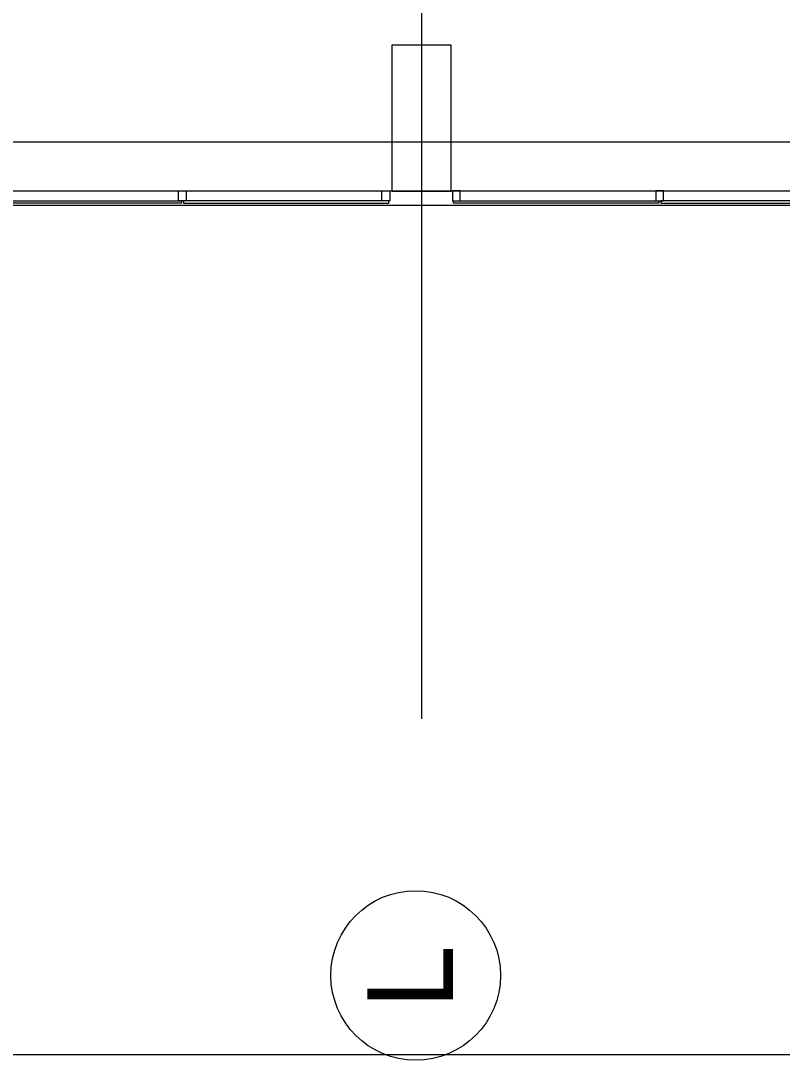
# Model space of a CAD drawing. Extents: x -264205 to -263659, y -1242401 to -1242060.
# Drawn here: x -263845.56 to -263837.78, y -1242250.2 to -1242239.57 of the extents above; entities that cross this region are included whole.
import ezdxf

# ---------------------------------------------------------------- set-up
doc = ezdxf.new("R2010")
doc.units = 0
for name, color, linetype in [('OBRUBNIKY_KOMUNIKACIE_PROJEKT', 7, 'Continuous'), ('OSI_STAVBY_KFA', 7, 'Continuous'), ('SITUACIA_DSP_2D', 7, 'Continuous')]:
    doc.layers.add(name, color=color, linetype=linetype)

msp = doc.modelspace()

# ---------------------------------------------------------------- linework, layer by layer
at = {"layer": 'OBRUBNIKY_KOMUNIKACIE_PROJEKT'}
msp.add_line((-263822.79, -1242241.457), (-263894.968, -1242241.457), dxfattribs=at)
at = {"layer": 'OSI_STAVBY_KFA'}
for p, q in [((-263841.468, -1242083.237), (-263841.468, -1242246.707)), ((-263792.653, -1242240.807), (-263911.523, -1242240.807))]:
    msp.add_line(p, q, dxfattribs=at)
msp.add_circle((-263841.528, -1242249.331), 0.867, dxfattribs=at)
at = {"layer": 'SITUACIA_DSP_2D'}
for p, q in [((-263841.768, -1242241.312), (-263841.768, -1242239.812)), ((-263841.768, -1242239.812), (-263841.168, -1242239.812)), ((-263841.168, -1242239.812), (-263841.168, -1242241.312)), ((-263894.581, -1242241.307), (-263822.79, -1242241.307)), ((-263843.953, -1242241.407), (-263843.953, -1242241.307)), ((-263843.953, -1242241.307), (-263843.873, -1242241.307)), ((-263843.873, -1242241.307), (-263843.873, -1242241.407)), ((-263841.873, -1242241.407), (-263841.873, -1242241.307)), ((-263841.873, -1242241.307), (-263841.793, -1242241.307)), ((-263841.793, -1242241.307), (-263841.793, -1242241.407)), ((-263841.168, -1242241.312), (-263841.768, -1242241.312)), ((-263841.073, -1242241.307), (-263841.153, -1242241.307)), ((-263841.153, -1242241.307), (-263841.153, -1242241.407)), ((-263841.073, -1242241.407), (-263841.073, -1242241.307)), ((-263838.993, -1242241.307), (-263839.073, -1242241.307)), ((-263839.073, -1242241.307), (-263839.073, -1242241.407)), ((-263838.993, -1242241.407), (-263838.993, -1242241.307)), ((-263822.79, -1242241.457), (-263894.968, -1242241.457)), ((-263846.023, -1242241.407), (-263843.923, -1242241.407)), ((-263843.923, -1242241.432), (-263846.023, -1242241.432)), ((-263843.913, -1242241.407), (-263843.953, -1242241.407)), ((-263843.923, -1242241.407), (-263843.923, -1242241.432)), ((-263843.873, -1242241.407), (-263843.913, -1242241.407)), ((-263841.803, -1242241.407), (-263843.903, -1242241.407)), ((-263843.903, -1242241.407), (-263843.903, -1242241.432)), ((-263843.903, -1242241.432), (-263841.803, -1242241.432)), ((-263841.833, -1242241.407), (-263841.873, -1242241.407)), ((-263841.793, -1242241.407), (-263841.833, -1242241.407)), ((-263841.803, -1242241.432), (-263841.803, -1242241.407)), ((-263841.153, -1242241.407), (-263841.113, -1242241.407)), ((-263841.143, -1242241.432), (-263841.143, -1242241.407)), ((-263841.143, -1242241.407), (-263839.043, -1242241.407)), ((-263839.043, -1242241.432), (-263841.143, -1242241.432)), ((-263841.113, -1242241.407), (-263841.073, -1242241.407)), ((-263839.073, -1242241.407), (-263839.033, -1242241.407)), ((-263839.043, -1242241.407), (-263839.043, -1242241.432)), ((-263839.033, -1242241.407), (-263838.993, -1242241.407)), ((-263836.923, -1242241.407), (-263839.023, -1242241.407)), ((-263839.023, -1242241.407), (-263839.023, -1242241.432)), ((-263839.023, -1242241.432), (-263836.923, -1242241.432)), ((-263924.143, -1242250.14), (-263822.79, -1242250.14))]:
    msp.add_line(p, q, dxfattribs=at)

# ---------------------------------------------------------------- texts
at = {"layer": 'OSI_STAVBY_KFA'}
msp.add_text('L', height=0.875, rotation=90, dxfattribs=at).set_placement((-263841.147, -1242249.671))

doc.saveas('drawing.dxf')
